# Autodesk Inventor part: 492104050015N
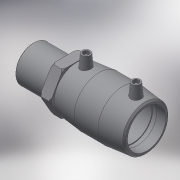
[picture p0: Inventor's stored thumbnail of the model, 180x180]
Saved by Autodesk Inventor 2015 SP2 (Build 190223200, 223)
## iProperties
Created: 2017-06
Part Number: 492104050015N
Material: Generic
Description: PLASSON Male Transition Coupler 50 x 11⁄2"
Document SubType Name: Modeling
Designer: KIM
Mass: 249.883 g
Surface Area: 624.94 cm^2
Volume: 249.883 cm^3
Density: 1 g/cm^3
Appearance: Default
Author: KIM
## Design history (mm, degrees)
derived "492104.ipt"
feature "Solid1::492104.ipt"
tag "TaggingFeature1"
body "Solid1"
other parameters: "d0" = 101, "d2" = 67, "d3" = 49, "d4" = 33.66667, "d5" = 60.3, "d6" = 47.5, "d8" = 168 deg, "d10" = 19.6, "d11" = 6.53333, "d29" = 51, "d30" = 14, "d31" = 35.35, "d34" = 5 deg, "d41" = 4, "d42" = 14, "d43" = 0, "d48" = 3, "d49" = 0, "d57" = 35, "d58" = 47.803, "d59" = 38.2424, "d60" = 56.7, "d61" = 67, "d62" = 0.95606, "d65" = 2.01, "d70" = 0.1, "d71" = 63, "d72" = 15.75, "d73" = 19.6, "d75" = 0, "L_" = 164, "L_1" = 49, "D_1" = 67, "A_" = 51, "d_2" = 12, "L_2" = 63, "D_" = 35, "R_" = 47.803
